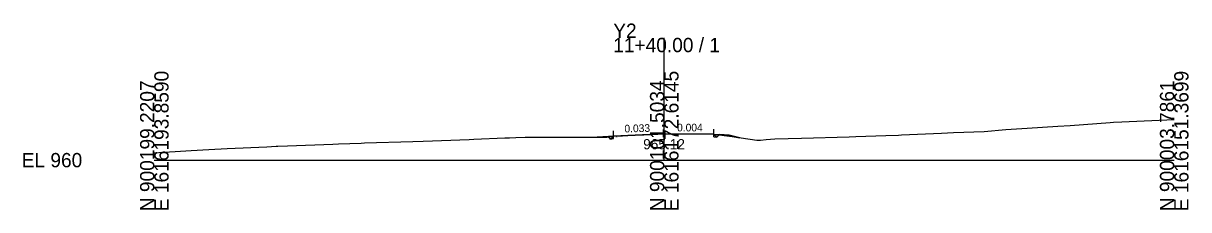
# Model space of a CAD drawing. Extents: x -26 to 1403, y -10 to 2517.
# Drawn here: x 1174.3 to 1402.8, y -9.7 to 26.8 of the extents above; entities that cross this region are included whole.
import ezdxf

# ---------------------------------------------------------------- set-up
doc = ezdxf.new("R2010")
doc.units = 0
for name, color, linetype in [('Exist Cross Section Cell', 7, 'Continuous'), ('Exist XS Center Line Elevation Label', 7, 'Continuous'), ('Exist XS Ground Line', 7, 'Continuous'), ('Prop XS Dump Level', 7, 'Continuous'), ('Prop XS Earthwork Shape', 7, 'Continuous'), ('Prop XS EOT Tick Mark', 7, 'Continuous'), ('Prop XS Finish Grade', 7, 'Continuous'), ('Prop XS Finish Grade Earthwork', 7, 'Continuous'), ('Prop XS Finish Grade Pavement', 7, 'Continuous'), ('Prop XS Pvmt Edge Slope', 7, 'Continuous'), ('Prop XS SE Text', 7, 'Continuous'), ('Prop XS Subgrade Earthwork', 7, 'Continuous')]:
    doc.layers.add(name, color=color, linetype=linetype)

msp = doc.modelspace()

# ---------------------------------------------------------------- linework, layer by layer
at = {"layer": 'Exist Cross Section Cell'}
for p, q in [((1300, 0), (1300, 23.93)), ((1200, 0), (1300, 0)), ((1300, 0), (1400, 0))]:
    msp.add_line(p, q, dxfattribs=at)
at = {"layer": 'Exist XS Ground Line'}
for p, q in [((1379.57, 6.81), (1387.43, 7.37)), ((1387.43, 7.37), (1388.12, 7.42)), ((1388.12, 7.42), (1389.75, 7.48)), ((1389.75, 7.48), (1400, 7.98)), ((1289.19, 4.57), (1290.03, 4.71)), ((1290.03, 4.71), (1291.83, 4.78)), ((1291.83, 4.78), (1293.57, 4.88)), ((1293.57, 4.88), (1295.99, 4.98)), ((1295.99, 4.98), (1300.1, 5.12)), ((1300.1, 5.12), (1302.68, 5.12)), ((1302.68, 5.12), (1309.73, 5.07)), ((1309.73, 5.07), (1313.34, 4.6)), ((1313.34, 4.6), (1318.12, 3.88)), ((1336.26, 4.54), (1337.54, 4.62)), ((1337.54, 4.62), (1343.42, 4.83)), ((1343.42, 4.83), (1345.94, 4.91)), ((1345.94, 4.91), (1346.49, 4.94)), ((1346.49, 4.94), (1354.35, 5.29)), ((1354.35, 5.29), (1356.72, 5.4)), ((1356.72, 5.4), (1362.76, 5.61)), ((1362.76, 5.61), (1366.96, 5.98)), ((1366.96, 5.98), (1371.16, 6.26)), ((1371.16, 6.26), (1377.19, 6.67)), ((1377.19, 6.67), (1379.57, 6.81)), ((1214.27, 2.25), (1222.07, 2.62)), ((1222.07, 2.62), (1223.89, 2.71)), ((1223.89, 2.71), (1224.24, 2.72)), ((1224.24, 2.72), (1226.12, 2.8)), ((1226.12, 2.8), (1235, 3.15)), ((1235, 3.15), (1236.13, 3.19)), ((1236.13, 3.19), (1240.58, 3.33)), ((1240.58, 3.33), (1241.23, 3.36)), ((1241.23, 3.36), (1250.7, 3.65)), ((1250.7, 3.65), (1252.69, 3.72)), ((1252.69, 3.72), (1261.71, 4.07)), ((1261.71, 4.07), (1262.67, 4.08)), ((1262.67, 4.08), (1268.72, 4.36)), ((1268.72, 4.36), (1269.64, 4.37)), ((1269.64, 4.37), (1270.89, 4.43)), ((1270.89, 4.43), (1272.72, 4.49)), ((1272.72, 4.49), (1274.57, 4.52)), ((1274.57, 4.52), (1276.48, 4.52)), ((1276.48, 4.52), (1278.47, 4.49)), ((1278.47, 4.49), (1279.4, 4.49)), ((1279.4, 4.49), (1282.22, 4.48)), ((1282.22, 4.48), (1285.26, 4.49)), ((1285.26, 4.49), (1288.72, 4.52)), ((1288.72, 4.52), (1289.19, 4.57)), ((1318.12, 3.88), (1318.87, 3.88)), ((1318.87, 3.88), (1320, 4.01)), ((1320, 4.01), (1321.7, 4.19)), ((1321.7, 4.19), (1326.91, 4.33)), ((1326.91, 4.33), (1336.26, 4.54)), ((1200, 1.41), (1201.73, 1.53)), ((1201.73, 1.53), (1202.96, 1.61)), ((1202.96, 1.61), (1204.06, 1.68)), ((1204.06, 1.68), (1207.21, 1.87)), ((1207.21, 1.87), (1210.71, 2.07)), ((1210.71, 2.07), (1214.27, 2.25))]:
    msp.add_line(p, q, dxfattribs=at)
at = {"layer": 'Prop XS Dump Level'}
for p, q in [((1300, 5.12), (1290.03, 4.71)), ((1309.73, 5.07), (1300, 5.12))]:
    msp.add_line(p, q, dxfattribs=at)
at = {"layer": 'Prop XS Earthwork Shape'}
for points in [[(1286.81, 4.5), (1288.72, 4.52), (1289.11, 4.56), (1289.06, 4.63)], [(1289.11, 4.56), (1289.19, 4.57), (1290.03, 4.71), (1289.43, 4.11)], [(1290.03, 4.22), (1290.03, 4.71), (1289.43, 4.11)], [(1309.73, 5.07), (1310.31, 4.49), (1309.73, 4.57)], [(1309.73, 5.07), (1310.76, 4.94), (1310.31, 4.49)], [(1310.76, 4.94), (1313.34, 4.6), (1314.82, 4.38), (1312.73, 4.9), (1310.83, 5.01)]]:
    msp.add_lwpolyline(points, close=True, dxfattribs=at)
at = {"layer": 'Prop XS EOT Tick Mark'}
for p, q in [((1290.03, 4.71), (1290.03, 5.71)), ((1309.73, 5.07), (1309.73, 6.07))]:
    msp.add_line(p, q, dxfattribs=at)
at = {"layer": 'Prop XS Finish Grade'}
for p, q in [((1290.03, 4.71), (1289.06, 4.63)), ((1309.73, 5.07), (1310.83, 5.01))]:
    msp.add_line(p, q, dxfattribs=at)
at = {"layer": 'Prop XS Finish Grade Earthwork'}
for p, q in [((1286.81, 4.5), (1289.06, 4.63)), ((1310.83, 5.01), (1312.73, 4.9)), ((1312.73, 4.9), (1314.82, 4.38))]:
    msp.add_line(p, q, dxfattribs=at)
at = {"layer": 'Prop XS Finish Grade Pavement'}
for p, q in [((1290.03, 4.71), (1300, 5.12)), ((1300, 5.12), (1309.73, 5.07))]:
    msp.add_line(p, q, dxfattribs=at)
at = {"layer": 'Prop XS Pvmt Edge Slope'}
for p, q in [((1290.03, 4.71), (1289.43, 4.11)), ((1309.73, 5.07), (1310.31, 4.49))]:
    msp.add_line(p, q, dxfattribs=at)
at = {"layer": 'Prop XS Subgrade Earthwork'}
for p, q in [((1289.43, 4.11), (1289.06, 4.63)), ((1290.03, 4.22), (1290.03, 4.71)), ((1309.73, 4.57), (1309.73, 5.07)), ((1309.73, 4.57), (1310.31, 4.49)), ((1310.31, 4.49), (1310.83, 5.01)), ((1290.03, 4.22), (1289.43, 4.11))]:
    msp.add_line(p, q, dxfattribs=at)

# ---------------------------------------------------------------- texts
at = {"layer": 'Exist Cross Section Cell'}
for s, p in [('Y2', (1290, 23.93)), ('11+40.00 / 1', (1290, 21.13)), ('EL 960', (1174, -1.4))]:
    msp.add_text(s, height=2.8, dxfattribs=at).set_placement(p)
for s, p in [('E 1616193.8590', (1202.8, -10)), ('E 1616172.6145', (1302.8, -10)), ('E 1616151.3699', (1402.8, -10)), ('N 900199.2207', (1200, -10)), ('N 900101.5034', (1300, -10)), ('N 900003.7861', (1400, -10))]:
    msp.add_text(s, height=2.8, rotation=90, dxfattribs=at).set_placement(p)
at = {"layer": 'Exist XS Center Line Elevation Label'}
msp.add_text('965.12', height=2, dxfattribs=at).set_placement((1295.87, 2.12))
at = {"layer": 'Prop XS Dump Level'}
for s, height, p in [('Eop', 0.3, (1290.15, 4.46)), ('Eop', 0.3, (1309.69, 4.75)), ('Case1', 0.04, (1313.25, 4.92))]:
    msp.add_text(s, height=height, dxfattribs=at).set_placement(p)
at = {"layer": 'Prop XS SE Text'}
for s, rotation, p in [('0.033', 1.5533, (1292.21, 5.41)), ('0.004', 0.1074, (1302.52, 5.62))]:
    msp.add_text(s, height=1.5, rotation=rotation, dxfattribs=at).set_placement(p)

doc.saveas('drawing.dxf')
